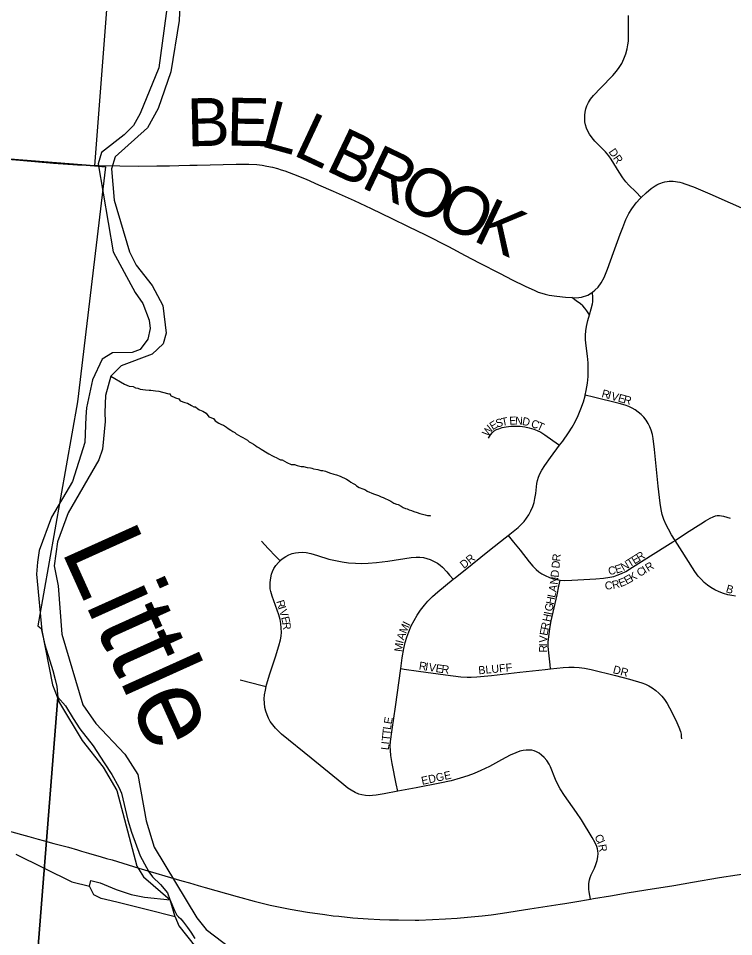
# Model space of a CAD drawing. Extents: x 1410790 to 1770854, y 448063 to 770588.
# Drawn here: x 1530950 to 1535419, y 593697 to 599435 of the extents above; entities that cross this region are included whole.
import ezdxf

# ---------------------------------------------------------------- set-up
doc = ezdxf.new("R2010")
doc.units = 0
for name, color, linetype in [('GM_X_County_Road', 7, 'Continuous'), ('GM_X_County_Road_Text', 7, 'Continuous'), ('GM_X_Major_River', 7, 'Continuous'), ('GM_X_Major_River_Text', 7, 'Continuous'), ('GM_X_Minor_River', 7, 'Continuous'), ('GM_X_Section', 7, 'Continuous'), ('GM_X_State_Route', 7, 'Continuous'), ('GM_X_Township_Subdivision', 7, 'Continuous'), ('GM_X_Township_Subdivision_Text', 7, 'Continuous')]:
    doc.layers.add(name, color=color, linetype=linetype)

msp = doc.modelspace()

# ---------------------------------------------------------------- linework, layer by layer
at = {"layer": 'GM_X_County_Road'}
for points in [[(1530758.5, 598564.8), (1530958, 598548.9), (1531170.3, 598529.5), (1531320.1, 598518.8), (1531445.4, 598515.2), (1531582.9, 598513.6), (1531700.8, 598512), (1531815.5, 598512.5), (1531894, 598513.6), (1531952.2, 598515.1), (1532021.6, 598516.9), (1532068, 598518.2), (1532147.6, 598520.3), (1532228.7, 598522.4), (1532311.3, 598523.9), (1532389.5, 598523.9), (1532439.4, 598521), (1532472.7, 598516.6), (1532503.1, 598511.6), (1532537.9, 598504.3), (1532568.9, 598496.7), (1532592.9, 598489.1), (1532613.8, 598481.8), (1532669.1, 598461.4), (1532747.1, 598429.7), (1532826, 598395), (1532917.2, 598354.4), (1533047.6, 598295.8), (1533154, 598247.3), (1533283.6, 598184.3), (1533385.9, 598134.1), (1533494.8, 598081.2), (1533638.3, 598008.4), (1533741.9, 597951.9), (1533828.8, 597907), (1533959.8, 597840.4), (1534034.4, 597801.3), (1534116.2, 597762.2), (1534176.3, 597734), (1534198.7, 597724.6), (1534221.2, 597717.3), (1534242.1, 597710.8), (1534266.8, 597705), (1534314.5, 597697.8), (1534368.4, 597691.9), (1534408.5, 597689.4)], [(1534842.1, 598315.9), (1534872.6, 598345.2), (1534903.3, 598370.5), (1534928, 598387.5), (1534939.7, 598394.1), (1534951.8, 598400), (1534963.4, 598404.9), (1534973.8, 598408.2), (1534989, 598412.3), (1535003.4, 598414.8), (1535016.8, 598416.5), (1535030.1, 598416.9), (1535042.1, 598416.7), (1535056.9, 598415.3), (1535068.8, 598413.4), (1535083.2, 598410.5), (1535097.2, 598406.5), (1535115.2, 598401.3), (1535167.8, 598381.5), (1535270.5, 598337.6), (1535759.6, 598121.5)], [(1534537.4, 597723.8), (1534552.1, 597735.2), (1534572.4, 597755.7), (1534591.2, 597781.5), (1534609.3, 597815.7), (1534630, 597867.1), (1534668.8, 597971.6), (1534710.4, 598085.5), (1534726, 598128.4), (1534746, 598177.2), (1534765.2, 598215.7), (1534782.7, 598243.9), (1534810.4, 598281.1), (1534834.4, 598308.5), (1534842.1, 598315.9)], [(1534408.5, 597689.4), (1534417.1, 597688.8), (1534452.4, 597690.1), (1534467.5, 597692.6), (1534481, 597696), (1534496, 597700.8), (1534507.2, 597705.3), (1534531.9, 597719.6), (1534537.4, 597723.8)]]:
    msp.add_lwpolyline(points, dxfattribs=at)
at = {"layer": 'GM_X_Major_River'}
for points in [[(1531965, 599668.5), (1531953.8, 599422.2), (1531903, 599100.5), (1531824.1, 598871.7), (1531757.5, 598750.8), (1531555.4, 598568.7), (1531531.8, 598495), (1531547.7, 598298.2), (1531645.2, 597975.3), (1531685.5, 597892.3), (1531785, 597765.8), (1531852.5, 597640), (1531872.9, 597467.2), (1531855.5, 597401.4), (1531786, 597336.7), (1531592.2, 597262.8), (1531526.8, 597198), (1531494.2, 597078.4), (1531490, 596972.3), (1531492.8, 596916.1), (1531475.2, 596742), (1531451.8, 596676.4), (1531260.6, 596345.7), (1531194.7, 596164.7), (1531173.5, 596014.8), (1531198.9, 595887.9), (1531221.8, 595586.5)], [(1531893.9, 599622), (1531827.4, 599126.2), (1531711.3, 598840), (1531669.7, 598764.7), (1531610.3, 598705.9), (1531469.9, 598596.6), (1531448.3, 598524.9), (1531543, 597975.5), (1531679.9, 597722), (1531726.5, 597652.8), (1531766.4, 597549.7), (1531773.4, 597497.4), (1531757.9, 597429.6), (1531710.5, 597366.4), (1531660.1, 597347.5), (1531537.8, 597344.1), (1531472.9, 597305.4), (1531412.1, 597176.4), (1531376.4, 597000.8), (1531371.2, 596944.8), (1531365.9, 596784.5), (1531288.7, 596541.6), (1531157.8, 596317.8), (1531079.4, 596109), (1531069.8, 596037.1), (1531062.2, 595961.1), (1531096.2, 595610.6)], [(1531096.2, 595610.6), (1531163.5, 595271.2), (1531206, 595157.4), (1531349, 594922), (1531480, 594755.2), (1531565.7, 594609.9), (1531690.9, 594136.2), (1531730.9, 594070.6), (1531897.8, 593926.9)], [(1531221.8, 595586.5), (1531352.1, 595144.7), (1531434.6, 595027.6), (1531615.1, 594837.2), (1531695.3, 594710.2), (1531748.2, 594421.4), (1531799.1, 594255.2), (1532065.8, 593815), (1532123.6, 593740.9), (1532331.3, 593583.8)], [(1531929.6, 593821.4), (1531749.1, 593865.4), (1531657.4, 593889.4), (1531565.7, 593911.5), (1531468, 593935.6), (1531420.4, 593958.7), (1531393.3, 594011.5), (1531402.1, 594047.4), (1531461.9, 594032.1), (1531561.3, 593991.8), (1531654.8, 593959.7), (1531738.7, 593943.8), (1531897.8, 593926.9)], [(1531929.6, 593821.4), (1531897.8, 593926.9)], [(1531929.6, 593821.4), (1531951.9, 593764.5), (1532056, 593632.7)]]:
    msp.add_lwpolyline(points, dxfattribs=at)
at = {"layer": 'GM_X_Minor_River'}
for points in [[(1531526.8, 597198), (1531613.2, 597148.5), (1531641.2, 597136.1), (1531667.2, 597133.9), (1531681.1, 597125.7), (1531697.1, 597123.5), (1531711.1, 597117.4), (1531745.1, 597113), (1531767.1, 597110.8), (1531777.1, 597110.7), (1531807.1, 597106.3), (1531827.2, 597106.1), (1531851.1, 597097.9), (1531889.1, 597089.4), (1531899.1, 597089.3), (1531901, 597077.3), (1531930.9, 597062.9), (1531952.9, 597056.7), (1531960.8, 597044.6), (1531990.8, 597034.2), (1532006.7, 597030.1), (1532030.6, 597015.8), (1532046.6, 597007.6), (1532056.6, 597007.5), (1532070.5, 596995.3), (1532082.5, 596989.2), (1532092.4, 596985.1), (1532102.4, 596980.9), (1532112.4, 596974.8), (1532122.3, 596968.7), (1532140.2, 596944.5), (1532168.1, 596934.2), (1532180, 596920), (1532201.9, 596905.7), (1532219.8, 596897.5), (1532231.8, 596893.4), (1532249.7, 596879.2), (1532261.7, 596871), (1532277.6, 596860.8), (1532289.5, 596852.7), (1532301.5, 596846.5), (1532311.5, 596838.4), (1532325.4, 596830.2), (1532339.3, 596822.1), (1532353.3, 596815.9), (1532367.2, 596807.8), (1532381.2, 596799.6), (1532391.1, 596789.5), (1532405.1, 596781.3), (1532419, 596773.1), (1532431, 596765), (1532440.9, 596756.9), (1532454.9, 596750.7), (1532466.8, 596742.5), (1532504.7, 596720.1), (1532514.6, 596714), (1532538.5, 596701.7), (1532550.5, 596695.6), (1532560.5, 596691.5), (1532574.4, 596683.3), (1532588.4, 596677.1), (1532598.4, 596677), (1532628.3, 596658.7), (1532654.2, 596646.4), (1532676.2, 596646.1), (1532692.2, 596640), (1532716.2, 596633.7), (1532732.2, 596633.5), (1532754.2, 596627.3), (1532774.2, 596625.1), (1532784.2, 596625), (1532794.2, 596620.9), (1532820.2, 596616.6), (1532840.1, 596610.3), (1532852.2, 596610.2), (1532868.1, 596606), (1532894.1, 596595.8), (1532920, 596587.5), (1532938, 596583.3), (1532960, 596575), (1532999.9, 596554.6), (1533015.8, 596544.4), (1533027.7, 596536.2), (1533041.7, 596528.1), (1533053.6, 596521.9), (1533063.6, 596513.8), (1533079.5, 596503.6), (1533101.5, 596495.4), (1533119.4, 596489.2), (1533129.4, 596481), (1533169.3, 596464.6), (1533199.2, 596454.2), (1533217.2, 596444), (1533229.2, 596439.9), (1533245.1, 596431.7), (1533257.1, 596427.6), (1533277, 596417.3), (1533294.9, 596405.1), (1533312.9, 596398.9), (1533322.9, 596396.8), (1533340.8, 596386.6)], [(1533340.8, 596386.6), (1533354.8, 596378.4), (1533368.7, 596372.3), (1533378.7, 596370.2), (1533392.7, 596364), (1533406.7, 596359.9), (1533420.6, 596353.7), (1533442.6, 596347.4), (1533458.6, 596341.3), (1533474.6, 596337.1), (1533492.6, 596332.9), (1533506.5, 596328.7), (1533520.6, 596328.6), (1533524.9, 596327)], [(1530934.4, 594212), (1531283.7, 594039.9), (1531393.7, 594012.9)]]:
    msp.add_lwpolyline(points, dxfattribs=at)
at = {"layer": 'GM_X_Section'}
for points in [[(1526539, 604404.1), (1531843.9, 603964.4), (1531817.6, 603600.9), (1531425.6, 598513.1), (1526072.4, 598935.7)], [(1531425.6, 598513.1), (1531493.5, 598506), (1531320.1, 597039.4), (1531072, 595638.1), (1531091.6, 595622.1), (1531115.8, 595519.7), (1531165, 595358.9), (1531180.1, 595302.7), (1531189.3, 595260.5), (1531194.1, 595212.5), (1531196.1, 595192.4), (1531032, 593109.8), (1525633.9, 593593.6), (1526072.4, 598935.7)]]:
    msp.add_lwpolyline(points, close=True, dxfattribs=at)
msp.add_lwpolyline([(1531032, 593109.8), (1531196.1, 595192.4), (1531245.2, 595139.6), (1531291.8, 595060.8), (1531334.7, 594996.1), (1531416.8, 594888.6), (1531486.9, 594783.5), (1531533.7, 594710.7), (1531578.2, 594629.9), (1531593.6, 594593.7), (1531634.7, 594425), (1531657.3, 594348.6), (1531710.7, 594201.7), (1531749.5, 594129.1), (1531765, 594102.8), (1531788.5, 594070.4), (1531837.6, 594021.6), (1531880.7, 593970.9), (1531895.9, 593928.6), (1531924.8, 593860.1), (1531934.5, 593844), (1531940.3, 593831.8), (1531950, 593819.7), (1531965.8, 593807.4), (1531981.5, 593787.2), (1532006.9, 593754.7), (1532026.4, 593724.4), (1532051.7, 593686)], dxfattribs=at)
at = {"layer": 'GM_X_State_Route'}
msp.add_lwpolyline([(1530886.4, 594357.2), (1531015.9, 594321.6), (1531072.9, 594306.3), (1531104.5, 594297.8), (1531170.9, 594279.6), (1531262.5, 594255.2), (1531319.1, 594238.4), (1531344.1, 594230.9), (1531387.9, 594217.9), (1531466.3, 594195), (1531500.7, 594185.7), (1531535.5, 594175.9), (1531635.6, 594144.5), (1531701.8, 594125.7), (1531972.2, 594045.4), (1532019.5, 594032), (1532073, 594016.6), (1532117.3, 594004.6), (1532316.2, 593948.2), (1532423.5, 593918.4), (1532523.1, 593894.3), (1532648.7, 593869.5), (1532756.8, 593850.6), (1532864.5, 593835.2), (1532916.4, 593827.8), (1532952.2, 593824.4), (1533040, 593815), (1533135.1, 593807.7), (1533208.6, 593803.8), (1533269.1, 593802.7), (1533324.9, 593801.7), (1533429.6, 593800.2), (1533452.5, 593800.4), (1533537.6, 593804), (1533619.4, 593808), (1533691.3, 593813.1), (1533756.6, 593818.4), (1533848, 593826.7), (1533903.4, 593832.7), (1533974.7, 593842.5), (1534146.3, 593870.2), (1534227.4, 593882.5), (1534334.3, 593899.6), (1534363.4, 593904.1), (1534427.8, 593914.4), (1534525.8, 593931.3), (1534543.8, 593934.4), (1534648.8, 593952.2), (1534754.9, 593969.7), (1534870.7, 593990), (1535046.1, 594017.2), (1535162.4, 594037.6), (1535330.8, 594065.4), (1535551.1, 594100.4)], dxfattribs=at)
at = {"layer": 'GM_X_Township_Subdivision'}
for points in [[(1534842.1, 598315.9), (1534807.4, 598349.9), (1534765.1, 598391.5), (1534745.3, 598413.7), (1534727.2, 598437.5), (1534703.6, 598473.3), (1534654.3, 598554.5), (1534639.3, 598575.6), (1534618.6, 598600.3), (1534551.3, 598667.7), (1534534.3, 598688.2), (1534519.1, 598710.2), (1534507.7, 598730.7), (1534499.9, 598749.4), (1534494.1, 598768.7), (1534490.2, 598788.5), (1534488.4, 598808.6), (1534488.7, 598828.8), (1534491, 598848.9), (1534495.4, 598868.6), (1534501.9, 598887.7), (1534511.9, 598909), (1534524.4, 598929), (1534543.3, 598952.3), (1534588.9, 598999.9), (1534663.5, 599078.1), (1534687, 599105), (1534704.5, 599128.3), (1534719.7, 599153), (1534733.5, 599182.2), (1534744.7, 599212.5), (1534753.6, 599243.7), (1534758.7, 599269.1), (1534761.5, 599291.5), (1534762.9, 599320.6), (1534762.4, 599451.6)], [(1534519.1, 597583), (1534529.7, 597619.3), (1534537.3, 597651.6), (1534539, 597663.7), (1534539.9, 597676.8), (1534539.9, 597687.5), (1534537.4, 597723.8)], [(1534519.1, 597583), (1534501.1, 597607.7), (1534489.6, 597623.6), (1534476.6, 597638), (1534461.7, 597650.5), (1534435.4, 597669.7), (1534408.5, 597689.4)], [(1534491.7, 597079.4), (1534498.4, 597110.3), (1534505.5, 597155.4), (1534509.6, 597197.6), (1534511.1, 597239.8), (1534510.3, 597282.2), (1534506.8, 597324.4), (1534498.2, 597389.3), (1534493.9, 597425.4), (1534493, 597455.4), (1534494.9, 597482.1), (1534499.1, 597508.4), (1534508.6, 597546.9), (1534519.1, 597583)], [(1534331.8, 596766.9), (1534351.8, 596793.7), (1534387.6, 596844.4), (1534410.4, 596880.1), (1534429.3, 596914.3), (1534447.5, 596952.5), (1534464.8, 596994.8), (1534480, 597037.8), (1534490.8, 597075.4), (1534491.7, 597079.4)], [(1535053.8, 596172.9), (1535031.3, 596208.4), (1535011.4, 596242), (1534996.7, 596270.9), (1534983.2, 596303.9), (1534973.2, 596334.7), (1534965.7, 596366.3), (1534959.7, 596404.8), (1534948.3, 596512.2), (1534925.5, 596740.6), (1534917, 596809.2), (1534911.7, 596835.4), (1534904, 596860.9), (1534895.1, 596882.6), (1534884.3, 596903.4), (1534871.8, 596923.1), (1534857.5, 596941.7), (1534841.3, 596958.6), (1534823.6, 596974), (1534804.7, 596987.7), (1534784.7, 596999.8), (1534763.5, 597009.9), (1534741.6, 597018), (1534703.4, 597028.6), (1534543.7, 597066.9), (1534491.7, 597079.4)], [(1533886.6, 596811.3), (1533899.1, 596831.8), (1533911.9, 596846), (1533923.7, 596856.3), (1533936.8, 596864.6), (1533951.3, 596870.8), (1533972.9, 596877.2), (1533998.1, 596882.4), (1534027, 596885.9), (1534056.1, 596887.1), (1534085.2, 596885.8), (1534114, 596882.2), (1534142.4, 596876.1), (1534170.4, 596867.8), (1534191.3, 596859.7), (1534214.3, 596848), (1534239.1, 596832.7), (1534289.7, 596796.7), (1534331.8, 596766.9)], [(1534010.2, 596203.3), (1534072.6, 596254.3), (1534094.1, 596273.7), (1534109.4, 596290.2), (1534125.1, 596310.6), (1534139.1, 596332.2), (1534152.7, 596357.8), (1534164, 596384.5), (1534171.9, 596409), (1534177.6, 596434.1), (1534182.3, 596466.2), (1534189.6, 596528.2), (1534193.6, 596547.9), (1534199.4, 596567.2), (1534208.4, 596588.8), (1534220.9, 596612.5), (1534238.7, 596640.4), (1534275.1, 596691.3), (1534331.8, 596766.9)], [(1535053.8, 596172.9), (1535124.3, 596219.6), (1535213.3, 596275.6), (1535243.8, 596294.7), (1535272.2, 596311.8), (1535290.5, 596320.6), (1535306.8, 596326.1), (1535317.2, 596327.7), (1535331.1, 596327.5), (1535354.9, 596324.1), (1535397.3, 596311.7)], [(1533666.5, 595929.6), (1533678.4, 595939.3), (1533786.4, 596024.7), (1533893.9, 596110.8), (1533991.6, 596188.2), (1534010.2, 596203.3)], [(1534010.2, 596203.3), (1534043.4, 596162.1), (1534084.7, 596110.8), (1534141.4, 596038.6), (1534164.8, 596011.6), (1534185.4, 595990.9), (1534202.6, 595976.5), (1534221.2, 595963.9), (1534241, 595953.2), (1534267.7, 595941.5), (1534292.1, 595933.1), (1534314, 595927.8), (1534334.8, 595924.7)], [(1532584.9, 596045.4), (1532558.8, 596072.5), (1532510.6, 596122.5), (1532469.5, 596167.2)], [(1534334.8, 595924.7), (1534365.3, 595922.9), (1534407.7, 595923.6), (1534558.1, 595932.3), (1534606.8, 595936.6), (1534645.4, 595942.2), (1534670.6, 595947.7), (1534692.1, 595954.5), (1534718.9, 595965.7), (1534744.8, 595979.2), (1534786.6, 596004.6), (1534989.2, 596132.6), (1535039.4, 596163.4), (1535053.8, 596172.9)], [(1535431, 595825.1), (1535408.6, 595827.7), (1535383.3, 595832.8), (1535355.4, 595841.1), (1535328.2, 595851.6), (1535301.9, 595864.1), (1535276.7, 595878.6), (1535255.5, 595893.3), (1535235.6, 595909.8), (1535217.4, 595927.9), (1535198.5, 595950.1), (1535177.6, 595979.1), (1535083.9, 596125.4), (1535053.8, 596172.9)], [(1532584.9, 596045.4), (1532588.5, 596049), (1532604.2, 596061.6), (1532621.2, 596072.5), (1532639.3, 596081.6), (1532661.3, 596089.8), (1532680.9, 596094.8), (1532700.8, 596097.8), (1532724.4, 596098.5), (1532747.8, 596096.3), (1532777.2, 596090.3), (1532818.4, 596078.4), (1532890.4, 596056.4), (1532931.6, 596046.2), (1532973.1, 596038.2), (1533011.8, 596033), (1533057.3, 596029.4), (1533096.3, 596028.5), (1533135.4, 596029.9), (1533187.4, 596034.6), (1533258.7, 596043.9), (1533404.9, 596065.3), (1533434.8, 596067.6), (1533458.2, 596067.4), (1533481.5, 596064.9), (1533501.2, 596060.3), (1533523.4, 596052.5), (1533547.8, 596041.7), (1533568.1, 596029.9), (1533584.5, 596018.2), (1533599.5, 596004.8), (1533626.6, 595975.7), (1533643.8, 595955.8), (1533666.5, 595929.6)], [(1532498.3, 595259.8), (1532500.7, 595270.1), (1532521.5, 595339.4), (1532555.5, 595445.6), (1532577, 595514), (1532586.8, 595551.7), (1532590.9, 595573.8), (1532593.1, 595599.4), (1532592.9, 595625.1), (1532590.3, 595654), (1532585.6, 595679.3), (1532577.3, 595707.1), (1532535.2, 595824.3), (1532526.6, 595852.9), (1532523.3, 595869.5), (1532522.2, 595886.4), (1532523.2, 595909.8), (1532527, 595939.6), (1532532.2, 595962.5), (1532537.7, 595978.5), (1532546.6, 595996.7), (1532559.3, 596016.5), (1532574.2, 596034.7), (1532584.9, 596045.4)], [(1533339.5, 595372), (1533348.5, 595438.7), (1533358.4, 595497), (1533366.9, 595535.7), (1533376.1, 595567.4), (1533388.6, 595601.5), (1533404.4, 595637.9), (1533422.3, 595673.2), (1533440.7, 595704.6), (1533462.9, 595737.5), (1533487.1, 595768.9), (1533509, 595793.7), (1533537, 595821.6), (1533571.6, 595852.1), (1533666.5, 595929.6)], [(1534275.1, 595369.7), (1534272.3, 595395.5), (1534264, 595470.3), (1534261.1, 595509.1), (1534261, 595538.2), (1534263.4, 595570.4), (1534270.7, 595621.9), (1534279.8, 595669.9), (1534316.4, 595832.7), (1534327.3, 595887.4), (1534334.8, 595924.7)], [(1533320.4, 594605.4), (1533310.9, 594652.3), (1533285.7, 594777.7), (1533276.9, 594829.7), (1533274.1, 594859.5), (1533273.7, 594886.1), (1533275.8, 594915.9), (1533286.3, 594990.8), (1533307.1, 595133.4), (1533339.5, 595372)], [(1533339.5, 595372), (1533359.6, 595369.1), (1533450.5, 595356.2), (1533619.5, 595332.8), (1533713.9, 595321.2), (1533753.1, 595317.8), (1533779.2, 595317.8), (1533815.2, 595319.8), (1533906.4, 595329.5), (1534082.4, 595349.2), (1534242.2, 595366.3), (1534275.1, 595369.7)], [(1534275.1, 595369.7), (1534353.2, 595377.8), (1534389.1, 595380.7), (1534421.9, 595381), (1534454.6, 595378.8), (1534487.1, 595374.3), (1534528.9, 595365.7), (1534681.7, 595327.7), (1534767.5, 595305.8), (1534846.2, 595282.6), (1534867.7, 595274.7), (1534888.4, 595264.8), (1534910.9, 595251.2), (1534932.1, 595235.7), (1534951.8, 595218.4), (1534969.8, 595199.3), (1534986.2, 595178.8), (1535002.8, 595154.5), (1535019.2, 595126), (1535057.1, 595049.6), (1535077.5, 595004.8), (1535087.3, 594979.4), (1535090.5, 594962.5), (1535092.1, 594946.8), (1535092.5, 594932.5)], [(1532335.4, 595300.7), (1532472.8, 595266.2), (1532498.3, 595259.8)], [(1533320.4, 594605.4), (1533234.7, 594589.2), (1533186, 594580.6), (1533162.9, 594577.9), (1533142.8, 594577.3), (1533119.4, 594578.7), (1533096.2, 594582.6), (1533076.7, 594588), (1533055.1, 594597.3), (1533028.6, 594611.3), (1533009, 594624.1), (1532970.4, 594655), (1532780.3, 594811.1), (1532594.4, 594962.1), (1532572.2, 594982), (1532556, 594998.8), (1532539.1, 595019.5), (1532524.1, 595041.6), (1532512.9, 595062.1), (1532503.6, 595083.6), (1532496.1, 595105.7), (1532490.6, 595128.5), (1532487, 595155), (1532486.3, 595181.7), (1532488.3, 595208.4), (1532493, 595237.9), (1532498.3, 595259.8)], [(1534525.8, 593931.3), (1534517.4, 593977.7), (1534514.4, 593994.3), (1534513.4, 594011.3), (1534514.5, 594028.1), (1534518.7, 594051.3), (1534523.4, 594067.4), (1534529.9, 594082.9), (1534549.5, 594124.1), (1534558.8, 594148.2), (1534566.1, 594172.8), (1534570.2, 594194.8), (1534571.8, 594217), (1534571.1, 594232.7), (1534569.1, 594245), (1534564.8, 594260.1), (1534554.5, 594283.4), (1534535.4, 594317.3), (1534468.8, 594425.9), (1534438.1, 594472.1), (1534362.9, 594579.1), (1534336.1, 594620.6), (1534316.9, 594655.1), (1534305.8, 594679.1), (1534274.6, 594758.1), (1534266.2, 594775.3), (1534252.1, 594796.6), (1534235.7, 594816.2), (1534219.6, 594831.6), (1534204.3, 594842.9), (1534187.7, 594852), (1534173, 594857.4), (1534157.9, 594861), (1534142.2, 594862.9), (1534123.3, 594862.5), (1534104.3, 594860), (1534082.6, 594854.8), (1534058.4, 594846.3), (1534023.2, 594829.9), (1533968.2, 594801.3), (1533893.6, 594760), (1533840.3, 594734), (1533798.1, 594715.5), (1533757.9, 594700.6), (1533710.6, 594686), (1533653.2, 594671.2), (1533582.6, 594655.9), (1533434.5, 594626.9), (1533320.4, 594605.4)]]:
    msp.add_lwpolyline(points, dxfattribs=at)

# ---------------------------------------------------------------- texts
at = {"layer": 'GM_X_County_Road_Text'}
for s, rotation, p in [('B', 1.26466, (1532005.9, 598634.4)), ('E', 358.97995, (1532249.1, 598639.8)), ('L', 344.63682, (1532453.8, 598638.7)), ('L', 334.90997, (1532657.6, 598583.9)), ('B', 334.53464, (1532860.3, 598488.9)), ('R', 334.53567, (1533082.8, 598383)), ('O', 334.53384, (1533305.3, 598277)), ('O', 334.53747, (1533543.6, 598163.5)), ('K', 334.58157, (1533782.2, 598049.9))]:
    msp.add_text(s, height=300, rotation=rotation, dxfattribs=at).set_placement(p)
at = {"layer": 'GM_X_Major_River_Text'}
msp.add_text('Little', height=499.92, rotation=294.27233, dxfattribs=at).set_placement((1531213.9, 596114.5))
at = {"layer": 'GM_X_Township_Subdivision_Text'}
for s, rotation, p in [('DR', 304.50093, (1534635.8, 598600.7)), ('R', 344.63838, (1534590.7, 597069.1)), ('I', 344.64189, (1534628.9, 597058.6)), ('V', 344.64295, (1534650.2, 597052.8)), ('E', 344.63748, (1534692.6, 597041.1)), ('R', 345.04719, (1534726.9, 597031.7)), ('W', 54.519, (1533884.2, 596817.2)), ('E', 31.92429, (1533913.6, 596860.2)), ('S', 15.94164, (1533940.1, 596877.3)), ('T', 11.32868, (1533972.9, 596886.7)), ('E', 3.58145, (1534018.8, 596894.8)), ('N', 356.80744, (1534052.4, 596897)), ('D', 349.38236, (1534094.6, 596894.8)), ('C', 340.46298, (1534148.5, 596883.3)), ('T', 335.48821, (1534184.7, 596870.5)), ('R', 31.99894, (1534829.5, 596040.5)), ('DR', 38.66336, (1533733.6, 595993.3)), ('D', 84.28505, (1534330.3, 595995.7)), ('R', 84.30286, (1534334.6, 596039.5)), ('N', 30.25596, (1534730.4, 595980.2)), ('T', 31.90327, (1534769.7, 596003.2)), ('E', 32.01521, (1534799.7, 596021.8)), ('R', 31.36567, (1534885.2, 595975.3)), ('D', 84.29273, (1534324.6, 595938.8)), ('C', 9.83564, (1534639.6, 595956.1)), ('E', 17.67172, (1534685.9, 595964.7)), ('K', 30.59964, (1534782.8, 595913.6)), ('C', 31.33844, (1534832.5, 595943.2)), ('I', 31.37364, (1534866.4, 595963.8)), ('N', 83.65549, (1534319.6, 595894.5)), ('C', 1.87032, (1534615.1, 595865.8)), ('R', 12.99811, (1534665.2, 595868.5)), ('E', 21.29242, (1534711.3, 595879.7)), ('E', 29.28352, (1534751, 595895.7)), ('A', 79.45991, (1534311, 595847.2)), ('B', 344.05794, (1535367.4, 595849.5)), ('R', 287.40185, (1532560, 595791.4)), ('H', 78.25934, (1534294.7, 595768.6)), ('L', 78.26402, (1534303.6, 595811.7)), ('I', 287.39835, (1532571.8, 595753.6)), ('V', 287.39679, (1532578.4, 595732.6)), ('G', 78.25934, (1534285.7, 595725.5)), ('E', 282.92295, (1532591.3, 595691.6)), ('H', 78.26244, (1534272.3, 595660.8)), ('I', 78.29025, (1534281.3, 595704)), ('R', 277.45341, (1532598.9, 595658.6)), ('M', 66.95564, (1533372.4, 595586.3)), ('I', 63.66948, (1533392.7, 595634.2)), ('R', 78.29709, (1534261.6, 595609.1)), ('A', 71.49593, (1533358.8, 595545.5)), ('V', 87.10266, (1534253.4, 595532.6)), ('E', 79.89549, (1534255.5, 595574.8)), ('M', 83.05343, (1533347.4, 595474.4)), ('I', 75.28535, (1533353.4, 595525.1)), ('R', 89.81783, (1534253.3, 595471.6)), ('I', 89.82517, (1534253.4, 595511.2)), ('R', 351.39418, (1533450.1, 595366.5)), ('I', 351.35685, (1533489.3, 595360.6)), ('V', 351.40606, (1533511.1, 595357.3)), ('E', 351.38885, (1533554.6, 595350.7)), ('BLUFF', 5.3115, (1533826.2, 595335.8)), ('R', 353.3671, (1533591.2, 595345.2)), ('DR', 345.25276, (1534661.1, 595344.3)), ('E', 80.78022, (1533282.1, 595021.8)), ('L', 81.6516, (1533277, 594987.2)), ('T', 84.08823, (1533269.8, 594917.7)), ('T', 84.07648, (1533273.4, 594952.7)), ('L', 84.08823, (1533263.9, 594860.8)), ('I', 84.07835, (1533267.5, 594895.8)), ('EDGE', 12.1994, (1533473.1, 594644.8)), ('C', 294.43592, (1534548.4, 594322.9)), ('I', 293.8671, (1534564.7, 594286.9)), ('R', 279.49028, (1534572.7, 594270))]:
    msp.add_text(s, height=50, rotation=rotation, dxfattribs=at).set_placement(p)

doc.saveas('drawing.dxf')
